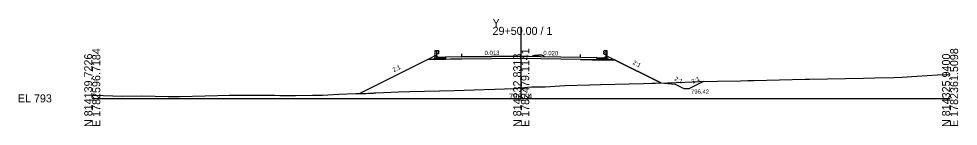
# Model space of a CAD drawing. Extents: x -12583 to 5303, y -44 to 25667.
# Drawn here: x 1974.3 to 2302.8, y -9.7 to 27.7 of the extents above; entities that cross this region are included whole.
import ezdxf

# ---------------------------------------------------------------- set-up
doc = ezdxf.new("R2010")
doc.units = 0
for name, color, linetype in [('Exist Cross Section Cell', 7, 'Continuous'), ('Exist XS Center Line Elevation Label', 7, 'Continuous'), ('Exist XS Ground Line', 7, 'Continuous'), ('Prop Conc 5in Monolithic Surface Mount Island', 7, 'Continuous'), ('Prop XS DDE', 7, 'Continuous'), ('Prop XS Ditch Standard Text', 7, 'Continuous'), ('Prop XS Dump Level', 7, 'Continuous'), ('Prop XS Earthwork Shape', 7, 'Continuous'), ('Prop XS EOT Tick Mark', 7, 'Continuous'), ('Prop XS Finish Grade', 7, 'Continuous'), ('Prop XS Finish Grade CurbGutter', 7, 'Continuous'), ('Prop XS Finish Grade Earthwork', 7, 'Continuous'), ('Prop XS Finish Grade Paved Shoulder', 7, 'Continuous'), ('Prop XS Finish Grade Pavement', 7, 'Continuous'), ('Prop XS Guardrail', 7, 'Continuous'), ('Prop XS Pvmt Edge Slope', 7, 'Continuous'), ('Prop XS SE Text', 7, 'Continuous'), ('Prop XS Side Slope Text', 7, 'Continuous'), ('Prop XS Subgrade CurbGutter', 7, 'Continuous'), ('Prop XS Subgrade Earthwork', 7, 'Continuous')]:
    doc.layers.add(name, color=color, linetype=linetype)

msp = doc.modelspace()

# ---------------------------------------------------------------- linework, layer by layer
at = {"layer": 'Exist Cross Section Cell'}
for p, q in [((2150, 0), (2150, 24.93)), ((2000, 0), (2150, 0)), ((2150, 0), (2300, 0))]:
    msp.add_line(p, q, dxfattribs=at)
at = {"layer": 'Exist XS Ground Line'}
for p, q in [((2231.38, 6.28), (2249.34, 6.64)), ((2249.34, 6.64), (2250.53, 6.66)), ((2250.53, 6.66), (2250.83, 6.67)), ((2250.83, 6.67), (2269.66, 7.09)), ((2269.66, 7.09), (2273.73, 7.18)), ((2273.73, 7.18), (2280.33, 7.32)), ((2280.33, 7.32), (2283.19, 7.43)), ((2283.19, 7.43), (2288.38, 7.7)), ((2288.38, 7.7), (2295.65, 8.17)), ((2295.65, 8.17), (2300, 8.31)), ((2126.61, 2.8), (2147.62, 3.4)), ((2147.62, 3.4), (2150, 3.64)), ((2150, 3.64), (2152.17, 3.85)), ((2152.17, 3.85), (2153.76, 4)), ((2153.76, 4), (2158.39, 4.05)), ((2158.39, 4.05), (2165.26, 4.43)), ((2165.26, 4.43), (2174, 4.72)), ((2174, 4.72), (2177.8, 4.85)), ((2177.8, 4.85), (2192.75, 5.17)), ((2192.75, 5.17), (2201.18, 5.44)), ((2201.18, 5.44), (2207.25, 5.7)), ((2207.25, 5.7), (2212.39, 5.83)), ((2212.39, 5.83), (2218.63, 6.01)), ((2218.63, 6.01), (2226.72, 6.15)), ((2226.72, 6.15), (2229.26, 6.23)), ((2229.26, 6.23), (2231.38, 6.28)), ((2000, 1.08), (2000.4, 1.06)), ((2000.4, 1.06), (2010.53, 0.8)), ((2010.53, 0.8), (2017.26, 0.87)), ((2017.26, 0.87), (2021.98, 0.71)), ((2021.98, 0.71), (2026.49, 0.63)), ((2026.49, 0.63), (2030.54, 0.68)), ((2030.54, 0.68), (2039.48, 0.89)), ((2039.48, 0.89), (2043.9, 1.04)), ((2043.9, 1.04), (2047.83, 1.11)), ((2047.83, 1.11), (2050.3, 1.12)), ((2050.3, 1.12), (2055.91, 1.13)), ((2055.91, 1.13), (2058.97, 1.14)), ((2058.97, 1.14), (2061.51, 1.06)), ((2061.51, 1.06), (2063.68, 1.09)), ((2063.68, 1.09), (2065.61, 1)), ((2065.61, 1), (2071.09, 1.01)), ((2071.09, 1.01), (2076.97, 1.06)), ((2076.97, 1.06), (2080.53, 1.16)), ((2080.53, 1.16), (2082.36, 1.25)), ((2082.36, 1.25), (2086.29, 1.47)), ((2086.29, 1.47), (2092.14, 1.66)), ((2092.14, 1.66), (2095.62, 1.75)), ((2095.62, 1.75), (2096.56, 1.79)), ((2096.56, 1.79), (2098.34, 1.87)), ((2098.34, 1.87), (2098.75, 1.89)), ((2098.75, 1.89), (2099.14, 1.92)), ((2099.14, 1.92), (2107.06, 2.31)), ((2107.06, 2.31), (2111.1, 2.34)), ((2111.1, 2.34), (2126.61, 2.8))]:
    msp.add_line(p, q, dxfattribs=at)
at = {"layer": 'Prop Conc 5in Monolithic Surface Mount Island'}
for p, q in [((2154, 14.83), (2154.76, 15.07)), ((2154, 14.67), (2154, 14.83)), ((2154.76, 15.07), (2156.01, 15.07)), ((2157.26, 15.02), (2156.01, 15.07)), ((2158, 14.75), (2157.26, 15.02)), ((2158, 14.59), (2158, 14.75))]:
    msp.add_line(p, q, dxfattribs=at)
at = {"layer": 'Prop XS DDE'}
for p, q in [((2198.8, 5.36), (2203.8, 4.95)), ((2203.8, 4.95), (2206.86, 3.42)), ((2206.86, 3.42), (2208.86, 3.42)), ((2213.77, 5.87), (2208.86, 3.42))]:
    msp.add_line(p, q, dxfattribs=at)
at = {"layer": 'Prop XS Dump Level'}
for p, q in [((2129.25, 14.49), (2150, 14.75)), ((2150, 14.75), (2170.75, 14.33))]:
    msp.add_line(p, q, dxfattribs=at)
at = {"layer": 'Prop XS Earthwork Shape'}
msp.add_lwpolyline([(2129.25, 13.7), (2125.25, 13.62), (2123.58, 13.58), (2119.19, 13.58), (2117.32, 13.58), (2093.55, 1.7), (2095.62, 1.75), (2096.56, 1.79), (2098.34, 1.87), (2098.75, 1.89), (2099.14, 1.92), (2107.06, 2.31), (2111.1, 2.34), (2126.61, 2.8), (2147.62, 3.4), (2150, 3.64), (2152.17, 3.85), (2153.76, 4), (2158.39, 4.05), (2165.26, 4.43), (2174, 4.72), (2177.8, 4.85), (2192.75, 5.17), (2198.8, 5.36), (2182.68, 13.42), (2180.81, 13.42), (2176.42, 13.42), (2174.75, 13.46), (2170.75, 13.54), (2150, 13.96)], close=True, dxfattribs=at)
at = {"layer": 'Prop XS EOT Tick Mark'}
for p, q in [((2129.25, 14.49), (2129.25, 15.49)), ((2170.75, 14.33), (2170.75, 15.33))]:
    msp.add_line(p, q, dxfattribs=at)
at = {"layer": 'Prop XS Finish Grade'}
for p, q in [((2117.32, 13.58), (2119.98, 14.91)), ((2120.56, 14.62), (2119.98, 14.91)), ((2179.44, 14.47), (2180.02, 14.76)), ((2180.02, 14.76), (2182.68, 13.42))]:
    msp.add_line(p, q, dxfattribs=at)
at = {"layer": 'Prop XS Finish Grade CurbGutter'}
for p, q in [((2121.25, 14.28), (2120.56, 14.62)), ((2123.58, 14.38), (2121.25, 14.28)), ((2176.42, 14.22), (2178.75, 14.13)), ((2178.75, 14.13), (2179.44, 14.47))]:
    msp.add_line(p, q, dxfattribs=at)
at = {"layer": 'Prop XS Finish Grade Earthwork'}
for p, q in [((2117.32, 13.58), (2093.55, 1.7)), ((2182.68, 13.42), (2198.8, 5.36))]:
    msp.add_line(p, q, dxfattribs=at)
at = {"layer": 'Prop XS Finish Grade Paved Shoulder'}
for p, q in [((2129.25, 14.49), (2123.58, 14.38)), ((2170.75, 14.33), (2176.42, 14.22))]:
    msp.add_line(p, q, dxfattribs=at)
at = {"layer": 'Prop XS Finish Grade Pavement'}
for p, q in [((2129.25, 14.49), (2150, 14.75)), ((2150, 14.75), (2129.25, 14.49)), ((2150, 14.75), (2170.75, 14.33))]:
    msp.add_line(p, q, dxfattribs=at)
at = {"layer": 'Prop XS Guardrail'}
for p, q in [((2119.93, 16.68), (2120.43, 16.68)), ((2119.93, 14.18), (2119.93, 16.68)), ((2120.43, 16.68), (2120.93, 16.68)), ((2120.43, 16.68), (2120.43, 14.18)), ((2120.93, 16.68), (2121.22, 16.48)), ((2121.22, 16.48), (2121.25, 16.42)), ((2179.07, 16.52), (2178.78, 16.32)), ((2179.57, 16.52), (2179.07, 16.52)), ((2180.07, 16.52), (2179.57, 16.52)), ((2179.57, 16.52), (2179.57, 14.02)), ((2180.07, 14.02), (2180.07, 16.52)), ((2120.93, 15.54), (2120.43, 15.54)), ((2121.22, 16.36), (2120.93, 16.16)), ((2120.93, 16.16), (2120.93, 16.06)), ((2120.93, 16.06), (2121.22, 15.86)), ((2121.22, 15.74), (2120.93, 15.54)), ((2121.25, 16.42), (2121.22, 16.36)), ((2121.22, 15.86), (2121.25, 15.8)), ((2121.25, 15.8), (2121.22, 15.74)), ((2178.78, 16.32), (2178.75, 16.26)), ((2178.75, 16.26), (2178.78, 16.2)), ((2178.78, 15.71), (2178.75, 15.65)), ((2178.75, 15.65), (2178.78, 15.59)), ((2178.78, 16.2), (2179.07, 16)), ((2179.07, 15.91), (2178.78, 15.71)), ((2178.78, 15.59), (2179.07, 15.39)), ((2179.07, 16), (2179.07, 15.91)), ((2179.07, 15.39), (2179.57, 15.39))]:
    msp.add_line(p, q, dxfattribs=at)
at = {"layer": 'Prop XS Pvmt Edge Slope'}
for p, q in [((2119.56, 13.96), (2119.19, 13.58)), ((2120.56, 13.96), (2119.56, 13.96)), ((2179.44, 13.8), (2180.44, 13.8)), ((2180.44, 13.8), (2180.81, 13.42))]:
    msp.add_line(p, q, dxfattribs=at)
at = {"layer": 'Prop XS Subgrade CurbGutter'}
for p, q in [((2120.56, 13.96), (2120.56, 14.62)), ((2123.58, 13.96), (2120.56, 13.96)), ((2123.58, 14.38), (2123.58, 13.96)), ((2176.42, 14.22), (2176.42, 13.8)), ((2176.42, 13.8), (2179.44, 13.8)), ((2179.44, 13.8), (2179.44, 14.47))]:
    msp.add_line(p, q, dxfattribs=at)
at = {"layer": 'Prop XS Subgrade Earthwork'}
for p, q in [((2119.19, 13.58), (2117.32, 13.58)), ((2123.58, 13.58), (2119.19, 13.58)), ((2125.25, 13.62), (2123.58, 13.58)), ((2129.25, 13.7), (2125.25, 13.62)), ((2150, 13.96), (2129.25, 13.7)), ((2170.75, 13.54), (2150, 13.96)), ((2170.75, 13.54), (2174.75, 13.46)), ((2174.75, 13.46), (2176.42, 13.42)), ((2176.42, 13.42), (2180.81, 13.42)), ((2180.81, 13.42), (2182.68, 13.42))]:
    msp.add_line(p, q, dxfattribs=at)

# ---------------------------------------------------------------- texts
at = {"layer": 'Exist Cross Section Cell'}
for s, p in [('Y', (2140, 24.93)), ('29+50.00 / 1', (2140, 22.13)), ('EL 793', (1974, -1.4))]:
    msp.add_text(s, height=2.8, dxfattribs=at).set_placement(p)
for s, p in [('E 1782596.7184', (2002.8, -10)), ('E 1782479.1141', (2152.8, -10)), ('E 1782361.5098', (2302.8, -10)), ('N 814139.7226', (2000, -10)), ('N 814232.8313', (2150, -10)), ('N 814325.9400', (2300, -10))]:
    msp.add_text(s, height=2.8, rotation=90, dxfattribs=at).set_placement(p)
at = {"layer": 'Exist XS Center Line Elevation Label'}
msp.add_text('796.64', height=2, dxfattribs=at).set_placement((2145.72, -0.36))
at = {"layer": 'Prop XS Ditch Standard Text'}
msp.add_text('796.42', height=1.5, dxfattribs=at).set_placement((2209.39, 1.59))
at = {"layer": 'Prop XS SE Text'}
for s, rotation, p in [('0.013', 0.7164, (2137.21, 15.09)), ('0.013', 0.7164, (2137.21, 15.09)), ('0.020', 358.8542, (2157.75, 15.09))]:
    msp.add_text(s, height=1.5, rotation=rotation, dxfattribs=at).set_placement(p)
at = {"layer": 'Prop XS Side Slope Text'}
for rotation, p in [(333.4349, (2188.84, 12.02)), (26.5651, (2105.44, 9.12)), (333.4349, (2203.46, 6.39)), (26.5651, (2210.03, 5.12))]:
    msp.add_text('2:1', height=1.5, rotation=rotation, dxfattribs=at).set_placement(p)

doc.saveas('drawing.dxf')
